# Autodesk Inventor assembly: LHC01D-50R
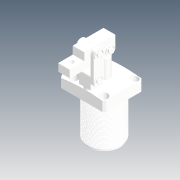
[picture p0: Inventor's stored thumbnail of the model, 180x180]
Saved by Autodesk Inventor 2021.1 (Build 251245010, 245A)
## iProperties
Created: 2019-04
Part Number: LHC01D-50R
Description: STEP AP214
Document SubType Name: Assembly
Designer: user
Title: LHC01D-50R.STEP
Revision Number: ÈÎºÎ
Sending System: SolidWorks 2016
Preprocessor: SwSTEP 2.0
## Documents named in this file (12)
- D:\Vault_2016\Projekty\Clamptek\Hydraulic\LHC01D\Inventor\LHC01D-50R\LHC01D-50R.iam
- D:\Vault_2016\Projekty\Clamptek\Hydraulic\LHC01D\Inventor\LHC01D-50R\LHC01D-50R(BT).ipt
- D:\Vault_2016\Projekty\Clamptek\Hydraulic\LHC01D\Inventor\LHC01D-50R\CPLCU-50-01_2.ipt
- D:\Vault_2016\Projekty\Clamptek\Hydraulic\LHC01D\Inventor\LHC01D-50R\CPLCU-50-02_2.ipt
- D:\Vault_2016\Projekty\Clamptek\Hydraulic\LHC01D\Inventor\LHC01D-50R\CPLCU-50-03_2.ipt
- D:\Vault_2016\Projekty\Clamptek\Hydraulic\LHC01D\Inventor\LHC01D-50R\CPLCU-50-04_2.ipt
- D:\Vault_2016\Projekty\Clamptek\Hydraulic\LHC01D\Inventor\LHC01D-50R\CPLCU-50-05_2.ipt
- D:\Vault_2016\Projekty\Clamptek\Hydraulic\LHC01D\Inventor\LHC01D-50R\CPLCU-50-07_2.ipt
- D:\Vault_2016\Projekty\Clamptek\Hydraulic\LHC01D\Inventor\LHC01D-50R\CPLCU-50-08_2.ipt
- D:\Vault_2016\Projekty\Clamptek\Hydraulic\LHC01D\Inventor\LHC01D-50R\M4ningjin_7.ipt
- D:\Vault_2016\Projekty\Clamptek\Hydraulic\LHC01D\Inventor\LHC01D-50R\¶ÂÍ·_12.ipt
- D:\Vault_2016\Projekty\Clamptek\Hydraulic\LHC01D\Inventor\LHC01D-50R\LHC01D050»îÈû¸Ë.ipt
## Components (24 placed, 24 different names)
1. LHC01D-50R(BT)_1
2. CPLCU-50-01_2_2
3. CPLCU-50-02_2_3
4. CPLCU-50-03_2_4
5. CPLCU-50-04_2_5
6. CPLCU-50-05_2_6
7. CPLCU-50-07_2_7
8. CPLCU-50-08_2_8
9. CPLCU-50-02_2_9
10. CPLCU-50-04_2_10
11. CPLCU-50-07_2_11
12. CPLCU-50-07_2_12
13. CPLCU-50-07_2_13
14. CPLCU-50-07_2_14
15. CPLCU-50-07_2_15
16. CPLCU-50-08_2_16
17. CPLCU-50-08_2_17
18. CPLCU-50-08_2_18
19. CPLCU-50-08_2_19
20. CPLCU-50-08_2_20
21. M4ningjin_7_21
22. ¶ÂÍ·_12_22
23. ¶ÂÍ·_12_23
24. LHC01D050»îÈû¸Ë_24
